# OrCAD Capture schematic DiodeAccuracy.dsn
size A
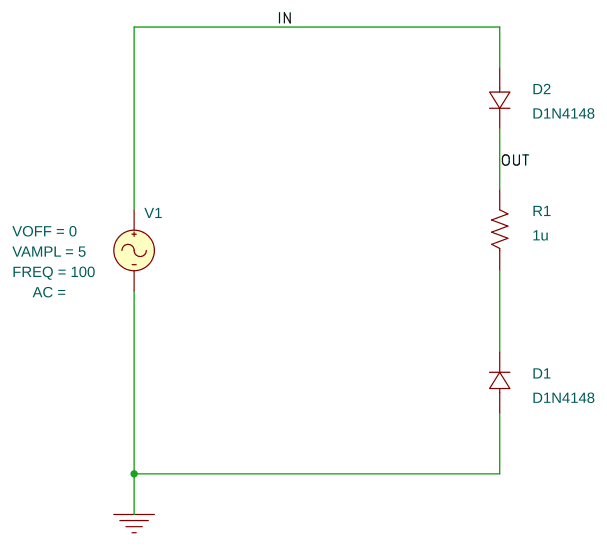
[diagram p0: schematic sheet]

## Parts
D1  D1N4148  [dax2do35]
D2  D1N4148  [dax2do35]
R1  1u  [AXRC05]
V1  VSIN

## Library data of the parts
D1 D2 = D1N4148
R1 = R
V1 = VSIN: FREQ: 100; VAMPL: 5; VOFF: 0

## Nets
0: D1.1 V1.2(-)
IN: D2.1 V1.1(+)
OUT: D2.2 R1.2
N00150: D1.2 R1.1
